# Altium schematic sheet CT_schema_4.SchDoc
size 136 x 123 mm
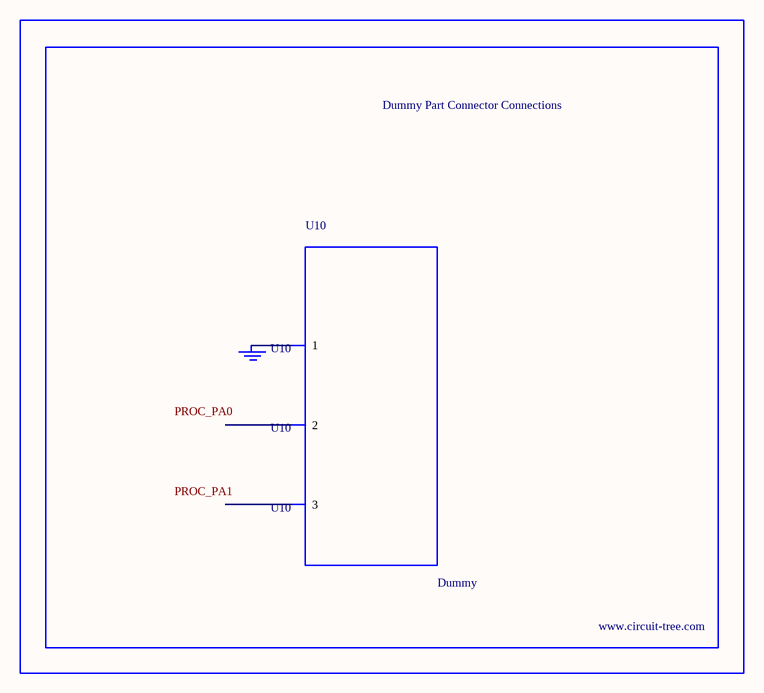
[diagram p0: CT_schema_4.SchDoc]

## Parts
BORDER3  (no value)
GND_INSTANCE_3_0  (no value)
U10  Dummy  [DUMMY_PACKAGE_103]

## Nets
NetGND_INSTANCE_3_0_0: GND_INSTANCE_3_0.0(GND) U10.1

Not connected (* = marked no-connect by the designer): U10 2 3

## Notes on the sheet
- Labels drawn without touching a wire or pin: PROC_PA0, PROC_PA1

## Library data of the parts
BORDER3 = BORDER_PAGE3
GND_INSTANCE_3_0 = GND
